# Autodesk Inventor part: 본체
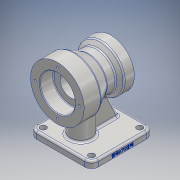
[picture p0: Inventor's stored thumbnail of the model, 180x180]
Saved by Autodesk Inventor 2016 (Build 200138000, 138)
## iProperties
Created: 2019-01
Part Number: 본체
Material: 알루미늄 6061
Document SubType Name: Modeling
Designer: USER
Density: 2.7 g/cm^3
Appearance: 알루미늄 - 평지
Mass: 898.816 g
Surface Area: 600.964 cm^2
Volume: 332.895 cm^3
Author: USER
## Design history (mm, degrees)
sketch "스케치1"
  geometry: L1 (-46, 46)-(46, 46); L2 (46, 46)-(46, -46); L3 (46, -46)-(-46, -46); L4 (-46, -46)-(-46, 46); 3 further points
  constraints: 8 end point, 2 midpoint, 2 parallel, 1 horizontal, 1 horizontal alignment, 1 perpendicular, 1 vertical alignment
  dimensions: "d0" = 92 distance of L2.end L3.end; "d1" = 92 distance of L1.end L2.end
extrude "돌출1" new body sketch "스케치1" distance "d2" = 10; taper "d3" = 0 deg
fillet "모깎기1" dims "d4" = 10
sketch "스케치2"
  geometry: L1 (-36, -46)-(36, -46) reference; L2 (46, -36)-(46, 36) reference; L3 (36, 46)-(-36, 46) reference; L4 (-46, 36)-(-46, -36) reference; A1 r 10 centre (-36, -36) between (-46, -36) and (-36, -46) reference; A2 r 10 centre (36, -36) between (36, -46) and (46, -36) reference; A3 r 10 centre (36, 36) between (46, 36) and (36, 46) reference; A4 r 10 centre (-36, 36) between (-36, 46) and (-46, 36) reference; 5 further points
  constraints: 4 coincident
hole "구멍1" sketch "스케치2" at (-36, 36), (36, 36), (36, -36), (-36, -36) diameter "d5" = 9; stored, may be unused: countersink angle "d9" = 90 deg, drill point angle "d11" = 118 deg; dims "d6" = 6, "d7" = 4, "d8" = 2, "d10" = 8
sketch "스케치3"
  geometry: L1 (-51, 80)-(29, 80); L2 (-46, 0)-(-46, 10) reference; L3 (-51, 120)-(-51, 106); L4 (-51, 106)-(-31, 106); L5 (-31, 106)-(-31, 96); L6 (-31, 96)-(12, 96); L7 (12, 96)-(12, 100); L8 (12, 100)-(29, 100); L9 (29, 100)-(29, 115); L10 (29, 115)-(14, 115); L11 (14, 115)-(8.126, 108); L12 (8.126, 108)-(-5.215, 108); L13 (-5.215, 108)-(-26, 120); L14 (-26, 120)-(-51, 120); 1 further point
  constraints: 27 end point, 7 perpendicular, 2 parallel, 1 horizontal, 1 vertical, 1 vertical alignment
  dimensions: "d12" = 5 distance from line of L2 L1.start; "d13" = 80 distance of L1.start L1.end; "d15" = 80 vertical distance of point (0, 0) L1.end; "d16" = 20 distance of L3.end L4.end; "d17" = 52 diameter of L4 L1; "d18" = 80 diameter of L14 L1; "d19" = 25 distance of L13.end L3.start; "d20" = 80 horizontal distance of L9.end L3.start; "d21" = 15 distance of L9.end L10.end; "d22" = 17 distance of L7.end L8.end; "d23" = 56 diameter of L12 L1; "d24" = 40 diameter of L8 L1; "d25" = 32 diameter of L6 L1; "d26" = 70 diameter of L10 L1; "d27" = 50 deg angle of L12 L11; "d28" = 30 deg angle of L12 L13
revolve "회전1" sketch "스케치3" stored, may be unused: angle "d29" = 90 deg
sketch "스케치4"
  geometry: L1 (36, -46)-(-36, -46) reference; C1 r 16 at (0, -16); 1 further point
  constraints: 1 centre point, 1 vertical alignment
  dimensions: "d30" = 32 diameter of C1; "d32" = 30 distance from line of L1 C1.centre
extrude "돌출2" join sketch "스케치4" stored distance "d33" = 10; taper "d34" = 0 deg
sketch "스케치5"
  geometry: L1 (36, 10)-(-36, 10) reference; L2 (36, 10)-(19.679, 45); L3 (14, 45)-(29, 45) reference; L4 (46, 10)-(46, 0) reference; 1 further point
  constraints: 2 end point, 2 point on line
  dimensions: "d35" = 10 distance from line of L4 L2.start; "d36" = 25 deg angle of L4 L2
feature "리브1" sketch "스케치5" dims "d37" = 1, "d38" = 10, "d39" = 0, "d40" = 0, "d41" = 1, "d42" = 1
sketch "스케치6"
  geometry: C1 r 40 at (0, 0) reference; C2 r 26 at (0, 0) reference; 2 further points
  constraints: 1 horizontal alignment
  dimensions: "d43" = 33 distance of C1.centre point (33, 0)
hole "구멍2" sketch "스케치6" at (33, 0) diameter "d44" = 3.242; stored, may be unused: countersink angle "d48" = 90 deg, drill point angle "d50" = 118 deg; dims "d45" = 9, "d46" = 4, "d47" = 2, "d49" = 11
sketch "스케치7"
  geometry: C1 r 20 at (0, 0) reference; C2 r 35 at (0, 0) reference; 2 further points
  constraints: 1 horizontal alignment
  dimensions: "d54" = 27.5 distance of C1.centre point (-27.5, 0)
hole "구멍3" sketch "스케치7" at (-27.5, 0) diameter "d55" = 3.242; stored, may be unused: countersink angle "d59" = 90 deg, drill point angle "d61" = 118 deg; dims "d56" = 9, "d57" = 4, "d58" = 2, "d60" = 11
fillet "모깎기2" dims "d65" = 1
fillet "모깎기3" dims "d66" = 0.6
chamfer "모따기1" distance "d67" = 1; stored, may be unused: second distance "d68" = 2, angle "d69" = 45 deg
fillet "모깎기4" dims "d70" = 3
fillet "모깎기5" dims "d71" = 3
fillet "모깎기6" dims "d72" = 3
sketch "스케치9"
  geometry: L1 (-7, -10)-(0, -10) reference; L2 (0, 72)-(0, 0) reference; 2 further points
  constraints: 1 other
  dimensions: "d73" = 46 distance from line of L1 point (-4, 36); "d74" = 4 distance from line of L2 point (-4, 36)
feature "엠보싱1" sketch "스케치9" dims "d0" = 92, "d1" = 92, "d75" = 0.5, "d76" = 0
node "솔리드1"
pattern_circular "원형 패턴1" dims angle "d52" = 360 deg
pattern_circular "원형 패턴2" dims angle "d63" = 360 deg
node "투영된 루프1"
node "투영된 루프2"
node "투영된 루프3"
